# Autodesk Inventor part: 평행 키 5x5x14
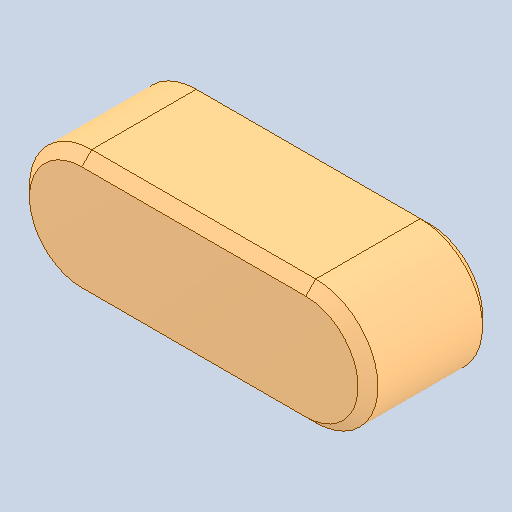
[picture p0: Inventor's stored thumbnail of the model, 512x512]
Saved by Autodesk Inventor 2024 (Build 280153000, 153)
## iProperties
Created: 2026-07
Part Number: 평행 키 5x5x14
Material: 강철, 연강
Document SubType Name: Modeling
Designer: com
Density: 7.86 g/cm^3
Appearance: 기본값
Author: jhkim
Revision Number: 1
Sending System: Autodesk Inventor 2027
Preprocessor: ST-DEVELOPER v20.1
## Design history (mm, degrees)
node "평행 키 5x5x141"
node "솔리드2"
node "솔리드1"
